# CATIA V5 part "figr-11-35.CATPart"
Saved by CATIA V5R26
Part number: Part1
Bounding box of the stored display mesh (mm): x -55 to 66, y 20 to 170, z -50 to 0
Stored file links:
  D:\_Deepak\CATIA\CATIA V5-6R2016_Deepak\Resources\Part files\Partfiles\c11_catia_v5_6r2016_prt\figr-11-35.CATPart
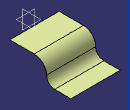
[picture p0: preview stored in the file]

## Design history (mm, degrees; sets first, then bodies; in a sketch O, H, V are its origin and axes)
Set1
  Extrude1: Element1 Sketch1, Lim1 66, Lim2 55, Direction yz-plane
  Symmetry1: ToTransfor Extrude1, Reference zx-plane
Body1 (main body)
  Sketch1 on yz-plane, origin (0, 0, 0), H (0, 1, 0), V (0, 0, 1)
    point P1 (20, 0)
    line L1 (20, 0) -> (80, 0)
    arc A1 centre (80, -30) radius 30 from (80, 0) to (110, -30) cw
    arc A2 centre (130, -30) radius 20 from (110, -30) to (130, -50) ccw
    line L2 (130, -50) -> (170, -50)
    coincidence: P1 H
    horizontal: L1 H
    tangency: A1 L1, A2 A1, L2 A2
